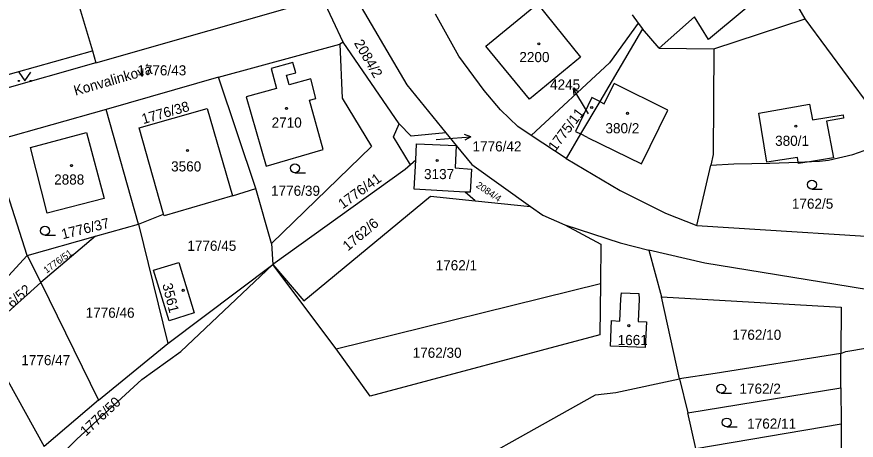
# Model space of a CAD drawing. Extents: x -679220 to -673243, y -1075091 to -1066557.
# Drawn here: x -676635.3 to -676494.4, y -1072401 to -1072330 of the extents above; entities that cross this region are included whole.
import ezdxf

# ---------------------------------------------------------------- set-up
doc = ezdxf.new("R2010")
doc.units = 0
for name, color, linetype in [('Hranice parcel', 7, 'Continuous'), ('Parcelní čísla', 7, 'Continuous'), ('Pop  PČ popisy', 7, 'Continuous'), ('Vnitřní kresba', 7, 'Continuous'), ('Značky budov', 7, 'Continuous'), ('Značky kultur', 7, 'Continuous')]:
    doc.layers.add(name, color=color, linetype=linetype)

msp = doc.modelspace()

# ---------------------------------------------------------------- linework, layer by layer
at = {"layer": 'Hranice parcel'}
for p, q in [((-676637.65, -1072284.57), (-676622.64, -1072335.67)), ((-676622.05, -1072337.69), (-676584, -1072326.79)), ((-676580.53, -1072334.19), (-676584, -1072326.79)), ((-676532.03, -1072329.62), (-676531.01, -1072331)), ((-676531.01, -1072331), (-676535.82, -1072337.69)), ((-676531.01, -1072331), (-676530.28, -1072331.99)), ((-676530.28, -1072331.99), (-676537.47, -1072344.17)), ((-676527.49, -1072335.21), (-676530.28, -1072331.99)), ((-676580.53, -1072334.19), (-676581.08, -1072334.53)), ((-676571.12, -1072347.95), (-676580.53, -1072334.19)), ((-676648.79, -1072343.03), (-676622.64, -1072335.67)), ((-676622.64, -1072335.67), (-676622.05, -1072337.69)), ((-676601.48, -1072340.1), (-676581.08, -1072334.53)), ((-676622.05, -1072337.69), (-676652.85, -1072346.45)), ((-676535.82, -1072337.69), (-676548.96, -1072349.89)), ((-676601.48, -1072340.1), (-676620.34, -1072345.53)), ((-676595.21, -1072358.8), (-676601.48, -1072340.1)), ((-676537.47, -1072344.17), (-676540.69, -1072349.62)), ((-676620.34, -1072345.53), (-676639.69, -1072351)), ((-676614.87, -1072364.77), (-676620.34, -1072345.53)), ((-676563.3, -1072349.45), (-676561.58, -1072351.56)), ((-676543.14, -1072353.76), (-676548.96, -1072349.89)), ((-676540.69, -1072349.62), (-676543.14, -1072353.76)), ((-676633.57, -1072370.04), (-676639.69, -1072351)), ((-676568.36, -1072354.03), (-676569.22, -1072354.79)), ((-676521.19, -1072365.02), (-676518.84, -1072354.84)), ((-676599.12, -1072360.03), (-676595.21, -1072358.8)), ((-676592.57, -1072368.02), (-676595.21, -1072358.8)), ((-676558.38, -1072360.83), (-676560.08, -1072359.37)), ((-676558.38, -1072360.83), (-676549.08, -1072361.78)), ((-676614.87, -1072364.77), (-676610.68, -1072363.07)), ((-676526.45, -1072362.91), (-676521.19, -1072365.02)), ((-676622.11, -1072366.81), (-676614.87, -1072364.77)), ((-676614.87, -1072364.77), (-676609.98, -1072384.83)), ((-676633.57, -1072370.04), (-676622.11, -1072366.81)), ((-676622.11, -1072366.81), (-676631.26, -1072374.57)), ((-676592.57, -1072368.02), (-676592.35, -1072371.56)), ((-676529.25, -1072369.16), (-676527.1, -1072376.98)), ((-676642.92, -1072380.09), (-676633.57, -1072370.04)), ((-676633.57, -1072370.04), (-676631.26, -1072374.57)), ((-676609.98, -1072384.83), (-676592.35, -1072371.56)), ((-676581.7, -1072385.68), (-676592.35, -1072371.56)), ((-676641.13, -1072383.33), (-676631.26, -1072374.57)), ((-676631.26, -1072374.57), (-676621.59, -1072394.33)), ((-676581.7, -1072385.68), (-676537.33, -1072374.74)), ((-676537.33, -1072374.74), (-676537.45, -1072383.35)), ((-676524.1, -1072390.75), (-676527.1, -1072376.98)), ((-676641.13, -1072383.33), (-676630.75, -1072402.09)), ((-676537.45, -1072383.35), (-676576.01, -1072393.65)), ((-676621.59, -1072394.33), (-676609.98, -1072384.83)), ((-676576.01, -1072393.65), (-676581.7, -1072385.68)), ((-676497.02, -1072392.27), (-676496.99, -1072386.47)), ((-676524.1, -1072390.75), (-676522.71, -1072396.46)), ((-676522.71, -1072396.46), (-676497.02, -1072392.27)), ((-676497.02, -1072392.27), (-676496.94, -1072398.28)), ((-676621.59, -1072394.33), (-676630.75, -1072402.09)), ((-676521.37, -1072402.42), (-676522.71, -1072396.46)), ((-676521.37, -1072402.42), (-676496.94, -1072398.28)), ((-676496.94, -1072398.28), (-676496.97, -1072404.35))]:
    msp.add_line(p, q, dxfattribs=at)
for points in [[(-676506.94, -1072323.45), (-676519.24, -1072333.79), (-676521.58, -1072329.95), (-676527.49, -1072335.21)], [(-676488.44, -1072349.97), (-676502.98, -1072330.28), (-676506.94, -1072323.45)], [(-676579.2, -1072325.41), (-676569.86, -1072341.39), (-676563.3, -1072349.45)], [(-676547.94, -1072327.79), (-676540.7, -1072336.71), (-676549.25, -1072343.79), (-676556.57, -1072334.88), (-676547.94, -1072327.79)], [(-676556.87, -1072342.33), (-676561.11, -1072336.55), (-676565.06, -1072329.52)], [(-676581.08, -1072334.53), (-676580.71, -1072343.59), (-676575.76, -1072351.71), (-676592.57, -1072368.02)], [(-676527.49, -1072335.21), (-676518.31, -1072335.33), (-676518.43, -1072353.09), (-676518.84, -1072354.84)], [(-676596.84, -1072343.37), (-676593.48, -1072355.02), (-676583.89, -1072352.23), (-676586.2, -1072343.94), (-676585.15, -1072343.65), (-676585.96, -1072340.36), (-676589.63, -1072341.39), (-676590.07, -1072339.78), (-676588.51, -1072339.34), (-676588.99, -1072337.62), (-676592.65, -1072338.64), (-676591.72, -1072341.98), (-676596.84, -1072343.37)], [(-676548.96, -1072349.89), (-676551.21, -1072348.4), (-676552.64, -1072347.04), (-676554.15, -1072345.56), (-676556.87, -1072342.33)], [(-676537.47, -1072344.17), (-676538.82, -1072343.5), (-676541.57, -1072349.19), (-676540.69, -1072349.62)], [(-676610.68, -1072363.07), (-676614.77, -1072348.59), (-676603.36, -1072345.34), (-676599.12, -1072360.03)], [(-676569.22, -1072354.79), (-676572.11, -1072350.11), (-676571.12, -1072347.95)], [(-676563.3, -1072349.45), (-676569.12, -1072350), (-676571.12, -1072347.95)], [(-676630.22, -1072362.94), (-676633.05, -1072351.88), (-676623.61, -1072349.37), (-676620.66, -1072360.48), (-676630.22, -1072362.94)], [(-676568.36, -1072354.03), (-676568.22, -1072351.27), (-676561.58, -1072351.56)], [(-676518.84, -1072354.84), (-676514.96, -1072354.66), (-676508.93, -1072354.55), (-676504.17, -1072354.34), (-676501.94, -1072354.24), (-676500.6, -1072354.18), (-676499.09, -1072354.05), (-676495.02, -1072353.07), (-676493.1, -1072352.38), (-676490.29, -1072350.84), (-676488.44, -1072349.97)], [(-676561.58, -1072351.56), (-676561.74, -1072355.32), (-676559.01, -1072355.55), (-676559.25, -1072359.42), (-676560.08, -1072359.37)], [(-676561.58, -1072351.56), (-676558.92, -1072354.75), (-676549.08, -1072361.78)], [(-676560.08, -1072359.37), (-676568.6, -1072358.91), (-676568.36, -1072354.03)], [(-676543.14, -1072353.76), (-676534.03, -1072359.11), (-676526.45, -1072362.91)], [(-676569.22, -1072354.79), (-676570.14, -1072355.59), (-676592.35, -1072371.56)], [(-676521.19, -1072365.02), (-676482.21, -1072367.44), (-676480.46, -1072364.89), (-676480.16, -1072362.19), (-676482.17, -1072359.23)], [(-676599.12, -1072360.03), (-676610.6, -1072363.35), (-676610.68, -1072363.07)], [(-676592.35, -1072371.56), (-676587.15, -1072377.64), (-676565.89, -1072360.06), (-676558.38, -1072360.83)], [(-676549.08, -1072361.78), (-676547.01, -1072363.28), (-676543.36, -1072364.86)], [(-676543.36, -1072364.86), (-676537.27, -1072368.14), (-676537.33, -1072374.74)], [(-676543.36, -1072364.86), (-676534.07, -1072367.9), (-676529.25, -1072369.16)], [(-676475.69, -1072378.53), (-676495.46, -1072375.29), (-676519.85, -1072371.33), (-676529.25, -1072369.16)], [(-676629.22, -1072404.9), (-676625.24, -1072400.86), (-676614.32, -1072390.86), (-676607.81, -1072386.16), (-676592.35, -1072371.56)], [(-676605.57, -1072379.66), (-676609.74, -1072381.02), (-676612.36, -1072372.48), (-676608.1, -1072371.23), (-676605.57, -1072379.66)], [(-676529.65, -1072381.19), (-676529.83, -1072385.48), (-676535.68, -1072385.24), (-676535.5, -1072380.97), (-676534.08, -1072381.03), (-676533.94, -1072377.28), (-676533.81, -1072376.3), (-676530.94, -1072376.4), (-676530.88, -1072377.39), (-676531.01, -1072381.14), (-676529.65, -1072381.19)], [(-676527.1, -1072376.98), (-676496.97, -1072378.7), (-676496.99, -1072386.47)], [(-676496.99, -1072386.47), (-676496.16, -1072386.14), (-676489.23, -1072385)], [(-676496.99, -1072386.47), (-676518.09, -1072389.87), (-676524.1, -1072390.75)], [(-676596.95, -1072485.83), (-676591.17, -1072459.32), (-676598.96, -1072427.43), (-676538.2, -1072393.4), (-676534.79, -1072393.04), (-676524.1, -1072390.75)]]:
    msp.add_lwpolyline(points, dxfattribs=at)
at = {"layer": 'Pop  PČ popisy'}
for p, q in [((-676540.39, -1072344.54), (-676541.94, -1072341.97)), ((-676541.94, -1072341.97), (-676540.99, -1072342.57)), ((-676541.94, -1072341.97), (-676541.85, -1072343.08)), ((-676539.39, -1072346.22), (-676540.39, -1072344.54)), ((-676559.14, -1072350.12), (-676560.17, -1072349.69)), ((-676564.93, -1072350.54), (-676562.13, -1072350.33)), ((-676562.13, -1072350.33), (-676559.14, -1072350.12)), ((-676559.14, -1072350.12), (-676560.1, -1072350.69))]:
    msp.add_line(p, q, dxfattribs=at)
at = {"layer": 'Vnitřní kresba'}
for p, q in [((-676518.31, -1072335.33), (-676502.98, -1072330.28)), ((-676536.72, -1072344.54), (-676535.04, -1072341.13)), ((-676526.04, -1072345.61), (-676535.04, -1072341.13)), ((-676537.47, -1072344.17), (-676536.72, -1072344.54)), ((-676530.48, -1072354.64), (-676526.04, -1072345.61)), ((-676510.79, -1072346.11), (-676502.26, -1072344.63)), ((-676502.26, -1072344.63), (-676501.78, -1072347.25)), ((-676509.44, -1072354.34), (-676510.79, -1072346.11)), ((-676501.78, -1072347.25), (-676496.64, -1072346.41)), ((-676496.55, -1072346.95), (-676499.41, -1072347.46)), ((-676496.64, -1072346.41), (-676496.55, -1072346.95)), ((-676499.41, -1072347.46), (-676498.27, -1072353.62)), ((-676539.51, -1072350.2), (-676540.69, -1072349.62)), ((-676539.51, -1072350.2), (-676530.48, -1072354.64)), ((-676504.28, -1072353.56), (-676509.44, -1072354.34)), ((-676504.17, -1072354.34), (-676504.28, -1072353.56)), ((-676498.27, -1072353.62), (-676501.94, -1072354.24)), ((-676504.13, -1072354.61), (-676504.17, -1072354.34)), ((-676501.94, -1072354.24), (-676504.13, -1072354.61))]:
    msp.add_line(p, q, dxfattribs=at)
at = {"layer": 'Značky budov'}
for centre in [(-676547.71, -1072334.5), (-676590.05, -1072345.33), (-676538.83, -1072345.19), (-676532.81, -1072346.16), (-676504.57, -1072348.32), (-676606.66, -1072352.41), (-676564.77, -1072354.07), (-676626.14, -1072354.94), (-676607.39, -1072375.88), (-676532.61, -1072381.81)]:
    msp.add_circle(centre, 0.175, dxfattribs=at)
at = {"layer": 'Značky kultur'}
for p, q in [((-676588.64, -1072356.13), (-676586.89, -1072356.13)), ((-676501.87, -1072358.88), (-676500.12, -1072358.88)), ((-676630.6, -1072366.63), (-676628.85, -1072366.63)), ((-676517.09, -1072393.14), (-676515.34, -1072393.14)), ((-676516.16, -1072398.82), (-676514.41, -1072398.82))]:
    msp.add_line(p, q, dxfattribs=at)
msp.add_lwpolyline([(-676634.98, -1072339.23), (-676633.98, -1072340.73), (-676632.98, -1072339.23)], dxfattribs=at)
for centre, radius in [((-676634.98, -1072340.73), 0.1), ((-676632.98, -1072340.73), 0.1), ((-676588.64, -1072355.38), 0.75), ((-676501.87, -1072358.13), 0.75), ((-676630.6, -1072365.88), 0.75), ((-676517.09, -1072392.39), 0.75), ((-676516.16, -1072398.07), 0.75)]:
    msp.add_circle(centre, radius, dxfattribs=at)

# ---------------------------------------------------------------- texts
at = {"layer": 'Parcelní čísla'}
for s, height, rotation, p in [('2084/2', 1.7, 300, (-676578.78, -1072334.36)), ('1776/38', 1.7, 16, (-676614.1, -1072347.98)), ('1775/11', 1.7, 53, (-676544.93, -1072352.66)), ('1776/41', 1.7, 36, (-676580.61, -1072362.29)), ('2084/4', 1.14, 326, (-676558.35, -1072358.49)), ('1776/37', 1.7, 14, (-676627.61, -1072367.32)), ('1762/6', 1.7, 40, (-676579.75, -1072369.37)), ('1776/51', 1.14, 36, (-676630.33, -1072373.09)), ('1776/52', 1.7, 41, (-676638.94, -1072381.42)), ('3561', 1.7, 284, (-676610.92, -1072374.9)), ('1776/50', 1.7, 43, (-676623.73, -1072400.46))]:
    msp.add_text(s, height=height, rotation=rotation, dxfattribs=at).set_placement(p)
for s, p in [('2200', (-676550.97, -1072337.56)), ('1776/43', (-676615.1, -1072339.79)), ('4245', (-676545.82, -1072342.18)), ('2710', (-676592.55, -1072348.56)), ('380/2', (-676536.52, -1072349.51)), ('380/1', (-676508.04, -1072351.62)), ('1776/42', (-676558.83, -1072352.56)), ('3560', (-676609.42, -1072355.92)), ('3137', (-676566.97, -1072357.21)), ('2888', (-676629.05, -1072358.12)), ('1776/39', (-676592.65, -1072360.01)), ('1762/5', (-676505.23, -1072362.18)), ('1776/45', (-676606.7, -1072369.25)), ('1762/1', (-676565.02, -1072372.52)), ('1776/46', (-676623.77, -1072380.49)), ('1661', (-676534.47, -1072385.07)), ('1762/10', (-676515.23, -1072384.19)), ('1762/30', (-676568.88, -1072387.21)), ('1776/47', (-676634.57, -1072388.45)), ('1762/2', (-676514.03, -1072393.24)), ('1762/11', (-676512.73, -1072399.11))]:
    msp.add_text(s, height=1.7, dxfattribs=at).set_placement(p)
at = {"layer": 'Pop  PČ popisy'}
msp.add_text('Konvalinková', height=1.7, rotation=16, dxfattribs=at).set_placement((-676625.48, -1072343.21))

doc.saveas('drawing.dxf')
